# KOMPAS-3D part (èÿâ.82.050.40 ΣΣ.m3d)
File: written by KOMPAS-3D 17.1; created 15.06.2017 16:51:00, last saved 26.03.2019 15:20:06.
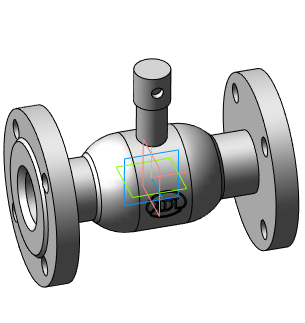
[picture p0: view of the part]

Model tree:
1. Операция без истории:2  (labels: Сталь 20  ГОСТ 1050-88)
